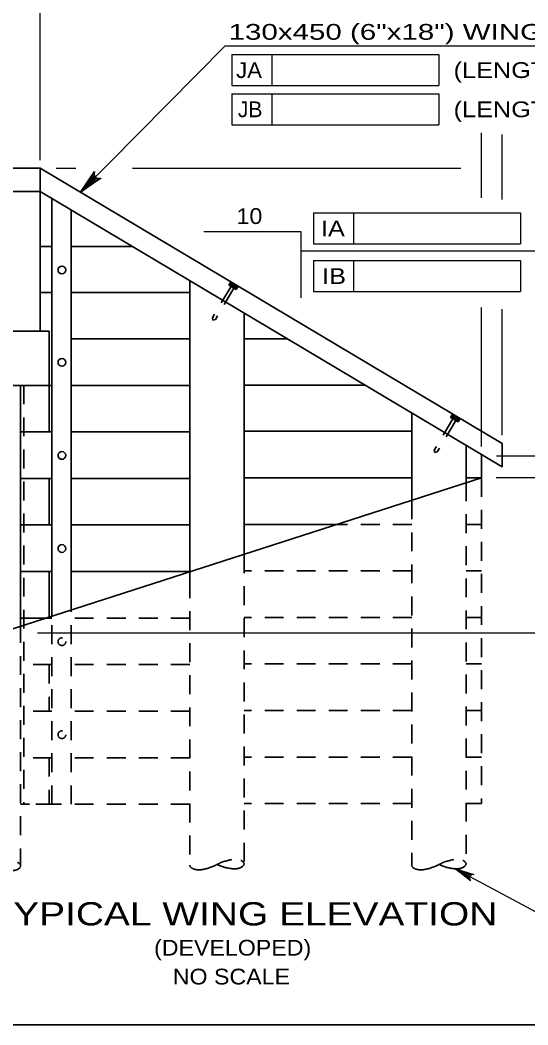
# Model space of a CAD drawing. Extents: x -6.4 to 73.1, y -66 to 0.
# Drawn here: x 16.45 to 20.32, y -21.25 to -13.6 of the extents above; entities that cross this region are included whole.
import ezdxf
from ezdxf.enums import TextEntityAlignment as Align

# ---------------------------------------------------------------- set-up
doc = ezdxf.new("R2010")
doc.units = 0
doc.header["$LTSCALE"] = 0.048
doc.header["$PDMODE"] = 32
doc.header["$PDSIZE"] = 0.024
doc.linetypes.add('MEDIUM_DASHED', pattern=[4.5, 3, -1.5])
for name, color, linetype, lineweight in [('1', 7, 'Continuous', 13), ('4', 7, 'Continuous', 25), ('5', 7, 'Continuous', 25)]:
    doc.layers.add(name, color=color, linetype=linetype, lineweight=lineweight)

msp = doc.modelspace()

# ---------------------------------------------------------------- hatches: boundary and pattern name
at = {"layer": '5'}
msp.add_hatch(color=256, dxfattribs=at).paths.add_polyline_path([(17.00225, -14.84392), (16.97533, -14.81733), (16.90917, -14.91133)])

# ---------------------------------------------------------------- linework, layer by layer
at = {"layer": '1', "lineweight": 35}
msp.add_lwpolyline([(1.75, -21.25), (33.25, -21.25), (33.25, -0.75), (1.75, -0.75)], close=True, dxfattribs=at)
at = {"layer": '4', "lineweight": 35}
for p, q in [((15.66475, -14.72783), (16.60142, -14.72783)), ((16.60142, -14.72783), (20.11833, -16.82475)), ((16.60142, -14.72783), (16.60142, -14.905)), ((14.76558, -14.905), (16.60142, -14.905)), ((16.60142, -14.905), (20.11833, -17.00192)), ((16.60142, -14.905), (16.60142, -15.968)), ((16.69108, -18.138), (16.69108, -14.9585)), ((16.83658, -18.09117), (16.83658, -15.04525)), ((16.69108, -15.32383), (16.60142, -15.32383)), ((17.30392, -15.32383), (16.83658, -15.32383)), ((17.74042, -15.58417), (17.74042, -17.85642)), ((18.03683, -15.61833), (18.052, -15.59275)), ((16.69108, -15.67542), (16.60142, -15.67542)), ((17.74042, -15.67542), (16.83658, -15.67542)), ((18.03683, -15.61833), (18.09442, -15.65267)), ((18.06258, -15.6195), (18.05633, -15.63)), ((18.05992, -15.6135), (18.08767, -15.63008)), ((18.08083, -15.63042), (18.07458, -15.64092)), ((18.08408, -15.6465), (18.09033, -15.63608)), ((18.09442, -15.65267), (18.10967, -15.62717)), ((18.15383, -15.83058), (18.15383, -17.66683)), ((14.64683, -15.968), (16.67033, -15.968)), ((16.67033, -15.968), (16.67033, -16.73567)), ((17.74042, -16.027), (16.83658, -16.027)), ((18.48433, -16.02775), (18.15383, -16.02775)), ((18.15383, -16.27833), (18.15383, -16.46583)), ((14.70908, -16.38133), (16.69108, -16.38133)), ((16.45267, -16.38133), (16.45267, -18.19792)), ((17.74042, -16.38133), (16.83658, -16.38133)), ((19.07408, -16.37933), (18.15383, -16.37933)), ((19.43083, -16.59208), (19.43083, -17.25633)), ((19.72642, -16.62575), (19.74158, -16.60017)), ((19.72642, -16.62575), (19.784, -16.66008)), ((19.75217, -16.62692), (19.74592, -16.63742)), ((19.7495, -16.62092), (19.77725, -16.6375)), ((19.77042, -16.63783), (19.76417, -16.64833)), ((19.77367, -16.65392), (19.77992, -16.6435)), ((19.784, -16.66008), (19.79925, -16.63458)), ((16.69108, -16.73567), (16.45267, -16.73567)), ((17.74042, -16.73567), (16.83658, -16.73567)), ((19.43083, -16.73092), (18.15383, -16.73092)), ((20.11833, -16.82475), (20.11833, -17.00192)), ((19.84425, -16.8385), (19.84425, -17.12125)), ((19.96233, -16.90892), (19.96233, -17.08525)), ((19.96233, -17.08525), (16.33033, -18.25408)), ((16.69108, -17.09), (16.45267, -17.09)), ((16.67033, -17.09), (16.67033, -17.44433)), ((17.74042, -17.09), (16.83658, -17.09)), ((19.43083, -17.08525), (18.15383, -17.08525)), ((19.96233, -17.08525), (19.84425, -17.08525)), ((18.86133, -17.43958), (18.15383, -17.43958)), ((16.69108, -17.44433), (16.45267, -17.44433)), ((17.74042, -17.44433), (16.83658, -17.44433)), ((16.69108, -17.79867), (16.45267, -17.79867)), ((16.67033, -17.79867), (16.67033, -18.153)), ((17.74042, -17.79867), (16.83658, -17.79867)), ((16.69108, -18.153), (16.45267, -18.153))]:
    msp.add_line(p, q, dxfattribs=at)
at = {"layer": '4', "linetype": 'MEDIUM_DASHED', "lineweight": 35}
for p, q in [((18.0545, -15.62892), (17.913, -15.86617)), ((18.07708, -15.64233), (17.93558, -15.87958)), ((16.47708, -16.38133), (16.47708, -19.57033)), ((19.74408, -16.63633), (19.60258, -16.87358)), ((19.76667, -16.64975), (19.62517, -16.887)), ((19.6065, -16.89117), (19.60258, -16.87358)), ((19.62517, -16.887), (19.6065, -16.89117)), ((19.84425, -17.11858), (19.84425, -20.02383)), ((19.96233, -17.08525), (19.96233, -19.5655)), ((19.43083, -17.25633), (19.43083, -20.03492)), ((19.43083, -17.43958), (18.86133, -17.43958)), ((19.96233, -17.43958), (19.84425, -17.43958)), ((18.15383, -17.66683), (18.15383, -20.02383)), ((19.43083, -17.79392), (18.15383, -17.79392)), ((19.96233, -17.79392), (19.84425, -17.79392)), ((17.74042, -17.85642), (17.74042, -20.03492)), ((16.83658, -19.57033), (16.83658, -18.09117)), ((16.45267, -18.19792), (16.45267, -20.0395)), ((16.69108, -19.57033), (16.69108, -18.138)), ((17.74042, -18.153), (16.83658, -18.153)), ((19.43083, -18.14825), (18.15383, -18.14825)), ((19.96233, -18.14825), (19.84425, -18.14825)), ((16.69108, -18.50733), (16.45267, -18.50733)), ((16.67033, -18.50733), (16.67033, -18.86167)), ((17.74042, -18.50733), (16.83658, -18.50733)), ((19.43083, -18.5025), (18.15383, -18.5025)), ((19.96233, -18.5025), (19.84425, -18.5025)), ((16.69108, -18.86167), (16.45267, -18.86167)), ((17.74042, -18.86167), (16.83658, -18.86167)), ((19.43083, -18.85683), (18.15383, -18.85683)), ((19.96233, -18.85683), (19.84425, -18.85683)), ((16.69108, -19.216), (16.45267, -19.216)), ((16.67033, -19.216), (16.67033, -19.57033)), ((17.74042, -19.216), (16.83658, -19.216)), ((19.43083, -19.21117), (18.15383, -19.21117)), ((19.96233, -19.21117), (19.84425, -19.21117)), ((17.74042, -19.57033), (16.45267, -19.57033)), ((16.56783, -19.57033), (16.745, -19.57033)), ((19.43083, -19.5655), (18.15383, -19.5655)), ((19.96233, -19.5655), (19.84425, -19.5655))]:
    msp.add_line(p, q, dxfattribs=at)
at = {"layer": '4', "lineweight": 35}
for points in [[(18.08408, -15.6465), (18.0475, -15.62467), (18.05375, -15.61425)], [(19.77367, -16.65392), (19.73708, -16.63208), (19.74333, -16.62167)]]:
    msp.add_lwpolyline(points, dxfattribs=at)
at = {"layer": '4', "linetype": 'MEDIUM_DASHED', "lineweight": 35}
msp.add_lwpolyline([(17.93558, -15.87958), (17.91692, -15.88375), (17.913, -15.86617)], dxfattribs=at)
at = {"layer": '4', "lineweight": 35}
for centre in [(16.76678, -15.50254), (16.76678, -16.20617), (16.76678, -16.91483), (16.76678, -17.62349)]:
    msp.add_circle(centre, 0.02953, dxfattribs=at)
at = {"layer": '4', "linetype": 'MEDIUM_DASHED', "lineweight": 35}
for centre in [(16.76678, -18.33215), (16.76678, -19.04081)]:
    msp.add_circle(centre, 0.02953, dxfattribs=at)
at = {"layer": '4', "lineweight": 35}
for centre, radius, start, end in [((18.05733, -15.61824), 0.00539, 346.64639, 131.74278), ((18.06498, -15.63628), 0.01696, 20.24459, 98.14459), ((18.08453, -15.63508), 0.00592, 61.02165, 127.90764), ((18.08453, -15.63508), 0.00592, 350.48153, 61.02165), ((19.74692, -16.62566), 0.00539, 346.64639, 131.74278), ((19.75457, -16.64369), 0.01696, 20.24459, 98.14459), ((19.77412, -16.64249), 0.00592, 61.02165, 127.90764), ((19.77412, -16.64249), 0.00592, 350.48153, 61.02165)]:
    msp.add_arc(centre, radius, start, end, dxfattribs=at)
at = {"layer": '4', "linetype": 'MEDIUM_DASHED', "lineweight": 35}
for centre, major_axis, start_param, end_param in [((16.37952, -20.0395), (0.07318, 0), 4.4555879, 8.1107827), ((17.81368, -20.03295), (-0.07323, -0.00196), 0, 1.8275974), ((17.73768, -19.93156), (-0.29233, -0.00784), 1.8903203, 2.3561945), ((18.15664, -20.12719), (0.29233, 0.00784), 1.8903203, 2.3561945), ((18.1511, -19.92048), (0.29233, 0.00784), 3.9269908, 4.392865), ((18.08064, -20.0258), (0.07323, 0.00196), 4.4555879, 8.1107827), ((19.50409, -20.03295), (-0.07323, -0.00196), 0, 1.8275974), ((19.4281, -19.93156), (-0.29233, -0.00784), 1.8903203, 2.3561945), ((19.84705, -20.12719), (0.29233, 0.00784), 1.8903203, 2.3561945), ((19.84151, -19.92048), (0.29233, 0.00784), 3.9269908, 4.392865), ((19.77106, -20.0258), (0.07323, 0.00196), 4.4555879, 8.1107827)]:
    msp.add_ellipse(centre, major_axis=major_axis, ratio=0.5, start_param=start_param, end_param=end_param, dxfattribs=at)
at = {"layer": '4'}
for p in [(18.06108, -15.61442), (18.06158, -15.61475), (18.062, -15.61567), (18.06208, -15.615), (18.0625, -15.616), (18.0625, -15.61667), (18.06258, -15.61533), (18.06308, -15.61567), (18.06308, -15.61633), (18.0635, -15.61658), (18.06358, -15.61592), (18.06408, -15.61625), (18.06467, -15.61658), (18.06283, -15.61892), (18.06292, -15.61767), (18.06292, -15.61825), (18.06292, -15.619), (18.063, -15.617), (18.06342, -15.61792), (18.06342, -15.61933), (18.0635, -15.61725), (18.0635, -15.618), (18.0635, -15.61858), (18.064, -15.61892), (18.06408, -15.61692), (18.06408, -15.61758), (18.06408, -15.61833), (18.06417, -15.617), (18.0645, -15.61858), (18.0645, -15.61925), (18.06458, -15.61792), (18.06467, -15.61725), (18.06508, -15.61825), (18.06508, -15.61892), (18.06517, -15.61758), (18.06525, -15.61692), (18.06558, -15.6185), (18.06558, -15.61917), (18.06567, -15.61783), (18.06575, -15.61717), (18.06608, -15.61883), (18.06617, -15.61817), (18.06625, -15.6175), (18.06667, -15.6185), (18.06667, -15.61917), (18.06675, -15.61783), (18.06717, -15.61875), (18.06717, -15.61942), (18.06725, -15.61808), (18.06767, -15.61908), (18.06775, -15.61842), (18.06825, -15.61867), (18.06825, -15.61942), (18.06875, -15.619), (18.06875, -15.61967), (18.06925, -15.61933), (18.06975, -15.61967), (18.07025, -15.61992), (18.07075, -15.62025), (18.07133, -15.6205), (18.07583, -15.62325), (18.07633, -15.62358), (18.07683, -15.62383), (18.07742, -15.62417), (18.07783, -15.62508), (18.07792, -15.6245), (18.07833, -15.62542), (18.07842, -15.62475), (18.07883, -15.62575), (18.07883, -15.62642), (18.07892, -15.62508), (18.07933, -15.626), (18.07933, -15.62667), (18.07942, -15.62533), (18.07975, -15.62767), (18.07983, -15.62633), (18.07983, -15.627), (18.07992, -15.62567), (18.08025, -15.628), (18.08025, -15.62858), (18.08033, -15.62733), (18.08042, -15.626), (18.08042, -15.62667), (18.08067, -15.62958), (18.08075, -15.62825), (18.08075, -15.62892), (18.08083, -15.62758), (18.08092, -15.62625), (18.08092, -15.62692), (18.08117, -15.62992), (18.08125, -15.62858), (18.08125, -15.62917), (18.08133, -15.62792), (18.08142, -15.62658), (18.08142, -15.62725), (18.08175, -15.6295), (18.08183, -15.62817), (18.08183, -15.62892), (18.08192, -15.62758), (18.082, -15.62692), (18.08225, -15.62917), (18.08233, -15.6285), (18.08242, -15.62717), (18.08242, -15.62783), (18.08283, -15.62883), (18.08292, -15.62817), (18.083, -15.6275), (18.08342, -15.62842), (18.08342, -15.62908), (18.0835, -15.62775), (18.08392, -15.62875), (18.084, -15.62808), (18.08442, -15.62908), (18.0845, -15.62842), (18.085, -15.62867), (18.0855, -15.629), (18.086, -15.62933), (19.75067, -16.62183), (19.75117, -16.62217), (19.75158, -16.62308), (19.75167, -16.62242), (19.75208, -16.62408), (19.75217, -16.62275), (19.75217, -16.62342), (19.75242, -16.62633), (19.7525, -16.62567), (19.7525, -16.62642), (19.75258, -16.62442), (19.75258, -16.62508), (19.75267, -16.62308), (19.75267, -16.62375), (19.753, -16.62533), (19.75308, -16.62467), (19.75308, -16.626), (19.75308, -16.62675), (19.75317, -16.62333), (19.75317, -16.624), (19.75317, -16.62542), (19.75358, -16.62633), (19.75367, -16.62367), (19.75367, -16.62433), (19.75367, -16.625), (19.75367, -16.62567), (19.75375, -16.62442), (19.75408, -16.62667), (19.75417, -16.62533), (19.75417, -16.626), (19.75425, -16.624), (19.75425, -16.62467), (19.75467, -16.62567), (19.75467, -16.62633), (19.75475, -16.625), (19.75483, -16.62433), (19.75517, -16.62592), (19.75517, -16.62658), (19.75525, -16.62525), (19.75533, -16.62458), (19.75567, -16.62625), (19.75575, -16.62558), (19.75583, -16.62492), (19.75625, -16.62592), (19.75625, -16.62658), (19.75633, -16.62525), (19.75675, -16.62617), (19.75675, -16.62683), (19.75683, -16.6255), (19.75725, -16.6265), (19.75733, -16.62583), (19.75783, -16.62608), (19.75783, -16.62683), (19.75833, -16.62642), (19.75833, -16.62708), (19.75883, -16.62675), (19.75942, -16.627), (19.75983, -16.62733), (19.76042, -16.62767), (19.76092, -16.62792), (19.7655, -16.63067), (19.76592, -16.63092), (19.7665, -16.63125), (19.767, -16.63158), (19.76742, -16.6325), (19.7675, -16.63192), (19.76792, -16.63283), (19.768, -16.63217), (19.76842, -16.63317), (19.76842, -16.63383), (19.7685, -16.6325), (19.76892, -16.63342), (19.76892, -16.63408), (19.769, -16.63275), (19.76933, -16.63508), (19.76942, -16.63375), (19.76942, -16.63442), (19.7695, -16.63308), (19.76983, -16.63542), (19.76983, -16.636), (19.76992, -16.63475), (19.77, -16.63342), (19.77, -16.63408), (19.77025, -16.637), (19.77033, -16.63567), (19.77033, -16.63633), (19.77042, -16.635), (19.7705, -16.63367), (19.7705, -16.63433), (19.77075, -16.63725), (19.77083, -16.636), (19.77083, -16.63658), (19.77092, -16.63533), (19.771, -16.634), (19.771, -16.63467), (19.77133, -16.63692), (19.77142, -16.63558), (19.77142, -16.63625), (19.7715, -16.63492), (19.77158, -16.63433), (19.77192, -16.63592), (19.77192, -16.63658), (19.772, -16.63458), (19.772, -16.63525), (19.77242, -16.63625), (19.7725, -16.63558), (19.77258, -16.63492), (19.773, -16.63583), (19.773, -16.6365), (19.77308, -16.63517), (19.7735, -16.63617), (19.77358, -16.6355), (19.774, -16.6365), (19.77408, -16.63583), (19.77458, -16.63608), (19.77508, -16.63642), (19.77558, -16.63675)]:
    msp.add_point(p, dxfattribs=at)
at = {"layer": '5'}
for p, q in [((16.60142, -14.66633), (16.60142, -12.91242)), ((16.90917, -14.91133), (18.00975, -13.797)), ((18.00975, -13.797), (21.75717, -13.797)), ((18.06192, -13.86317), (18.06192, -14.09942)), ((18.06192, -13.86317), (19.63675, -13.86317)), ((18.36442, -13.86317), (18.36442, -14.09942)), ((19.63675, -13.86317), (19.63675, -14.09942)), ((18.06192, -14.09942), (19.63675, -14.09942)), ((18.06192, -14.16175), (19.63675, -14.16175)), ((18.06192, -14.16175), (18.06192, -14.398)), ((18.36442, -14.16175), (18.36442, -14.398)), ((19.63675, -14.16175), (19.63675, -14.398)), ((18.06192, -14.398), (19.63675, -14.398)), ((19.96233, -14.95417), (19.96233, -14.45858)), ((20.11833, -14.96725), (20.11833, -14.47158)), ((16.72317, -14.72783), (16.87317, -14.72783)), ((17.304, -14.72783), (19.80533, -14.72783)), ((18.68367, -15.06875), (20.2585, -15.06875)), ((18.68367, -15.06875), (18.68367, -15.30492)), ((18.98617, -15.06875), (18.98617, -15.30492)), ((20.2585, -15.06875), (20.2585, -15.30492)), ((18.58975, -15.21317), (17.84642, -15.21317)), ((18.58975, -15.71458), (18.58975, -15.21317)), ((21.58333, -15.35933), (18.58975, -15.35933)), ((18.68367, -15.30492), (20.2585, -15.30492)), ((18.68367, -15.43117), (18.68367, -15.66742)), ((18.68367, -15.43117), (20.2585, -15.43117)), ((18.98617, -15.43117), (18.98617, -15.66742)), ((20.2585, -15.43117), (20.2585, -15.66742)), ((18.68367, -15.66742), (20.2585, -15.66742)), ((19.96233, -16.84742), (19.96233, -15.78883)), ((20.11833, -16.76125), (20.11833, -15.80192)), ((20.07542, -16.91775), (24.13342, -16.91775)), ((20.40433, -17.08525), (20.07292, -17.08525)), ((20.40433, -18.26842), (16.58125, -18.26842)), ((19.75925, -20.05875), (20.41433, -20.41075))]:
    msp.add_line(p, q, dxfattribs=at)
at = {"layer": '5', "lineweight": 35}
msp.add_line((16.69108, -15.662), (16.69108, -17.54525), dxfattribs=at)
at = {"layer": '5'}
for points in [[(16.90917, -14.91133), (17.01533, -14.75417), (17.01225, -14.77133), (17.016, -14.78542), (17.02333, -14.79575), (17.03375, -14.803), (17.04783, -14.8065), (17.065, -14.80325), (16.90917, -14.91133), (17.04783, -14.8065), (17.03375, -14.803), (16.90917, -14.91133), (17.02333, -14.79575), (17.016, -14.78542), (16.90917, -14.91133), (17.01225, -14.77133)], [(19.75925, -20.05875), (19.90383, -20.10467), (19.89, -20.10625), (19.88, -20.11225), (19.87375, -20.12025), (19.87058, -20.12992), (19.871, -20.1415), (19.87742, -20.154), (19.75925, -20.05875), (19.871, -20.1415), (19.87058, -20.12992), (19.75925, -20.05875), (19.87375, -20.12025), (19.88, -20.11225), (19.75925, -20.05875), (19.89, -20.10625)]]:
    msp.add_lwpolyline(points, dxfattribs=at)
msp.add_lwpolyline([(17.00225, -14.84392), (16.97533, -14.81733), (16.90917, -14.91133)], close=True, dxfattribs=at)

# ---------------------------------------------------------------- texts
for s, width, p in [('130x450 (6"x18") WING COPING', 1.4, (18.03608, -13.75025)), ('(LENGTH) WINGWALL A', 1.2, (19.74958, -14.04133)), ('(LENGTH) WINGWALL B', 1.2, (19.74958, -14.33992)), ('10', 1.1, (18.09675, -15.15283))]:
    msp.add_text(s, height=0.12, dxfattribs=dict(at, width=width)).set_placement(p)
for s, height, width, p in [('JA', 0.12, 1.05, (18.19175, -14.04133)), ('TYPICAL WING ELEVATION', 0.1772, 1.25, (18.14875, -20.49292)), ('(DEVELOPED)', 0.12, 1.1, (18.06696, -20.72242)), ('NO SCALE', 0.12, 1.1, (18.05746, -20.94217))]:
    msp.add_text(s, height=height, dxfattribs=dict(at, width=width)).set_placement(p, align=Align.CENTER)
msp.add_text('JB', height=0.12, dxfattribs=at).set_placement((18.20008, -14.33992), align=Align.CENTER)
at = {"layer": '5', "width": 1.2}
for s, p in [('IA', (18.83048, -15.24686)), ('IB', (18.83889, -15.60935))]:
    msp.add_text(s, height=0.12, rotation=359.938, dxfattribs=at).set_placement(p, align=Align.CENTER)

doc.saveas('drawing.dxf')
